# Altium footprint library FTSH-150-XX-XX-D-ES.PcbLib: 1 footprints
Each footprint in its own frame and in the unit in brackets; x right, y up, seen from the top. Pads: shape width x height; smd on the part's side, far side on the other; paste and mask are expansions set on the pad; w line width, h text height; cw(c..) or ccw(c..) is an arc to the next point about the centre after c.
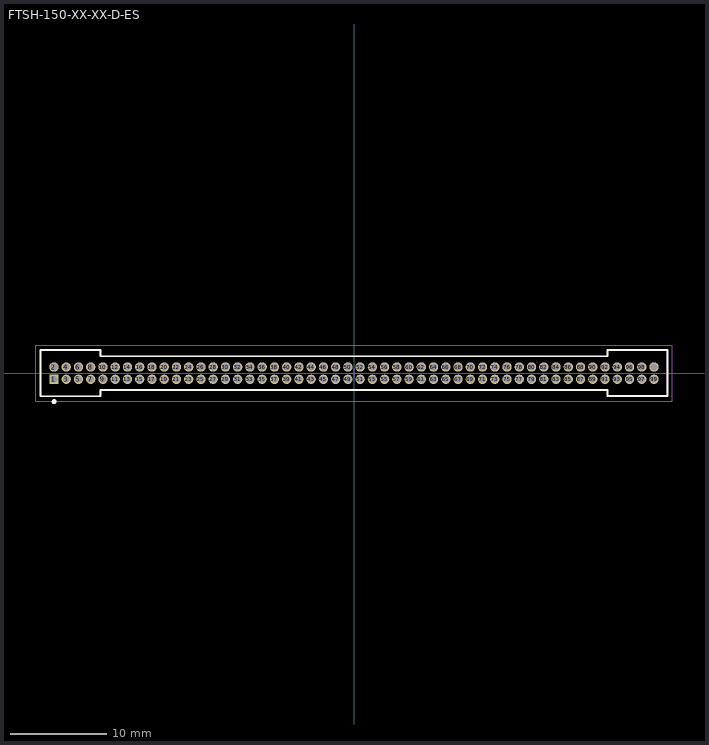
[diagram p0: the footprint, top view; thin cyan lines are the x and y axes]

## FTSH-150-XX-XX-D-ES [mil] "1.27mm pitch, 100 pin, terminal strip; w/end shrouds, PTH"
height 120.08
pads (100):
  rect 38x38 hole 28 unplated mask+0: 1(-1225,-25)
  round 38 hole 28 unplated mask+0: 2(-1225,25) 3(-1175,-25) 4(-1175,25) 5(-1125,-25) 6(-1125,25) 7(-1075,-25) 8(-1075,25) 9(-1025,-25) 10(-1025,25) 11(-975,-25) 12(-975,25) 13(-925,-25) 14(-925,25) 15(-875,-25) 16(-875,25) 17(-825,-25) 18(-825,25) 19(-775,-25) 20(-775,25) 21(-725,-25) 22(-725,25) 23(-675,-25) 24(-675,25) 25(-625,-25) 26(-625,25) 27(-575,-25) 28(-575,25) 29(-525,-25) 30(-525,25) 31(-475,-25) 32(-475,25) 33(-425,-25) 34(-425,25) 35(-375,-25) 36(-375,25) 37(-325,-25) 38(-325,25) 39(-275,-25) 40(-275,25) 41(-225,-25) 42(-225,25) 43(-175,-25) 44(-175,25) 45(-125,-25) 46(-125,25) 47(-75,-25) 48(-75,25) 49(-25,-25) 50(-25,25) 51(25,-25) 52(25,25) 53(75,-25) 54(75,25) 55(125,-25) 56(125,25) 57(175,-25) 58(175,25) 59(225,-25) 60(225,25) 61(275,-25) 62(275,25) 63(325,-25) 64(325,25) 65(375,-25) 66(375,25) 67(425,-25) 68(425,25) 69(475,-25) 70(475,25) 71(525,-25) 72(525,25) 73(575,-25) 74(575,25) 75(625,-25) 76(625,25) 77(675,-25) 78(675,25) 79(725,-25) 80(725,25) 81(775,-25) 82(775,25) 83(825,-25) 84(825,25) 85(875,-25) 86(875,25) 87(925,-25) 88(925,25) 89(975,-25) 90(975,25) 91(1025,-25) 92(1025,25) 93(1075,-25) 94(1075,25) 95(1125,-25) 96(1125,25) 97(1175,-25) 98(1175,25) 99(1225,-25) 100(1225,25)
Top Overlay:
  circle w9.84: c-1224.41,-116.14 r4.92
  lines w7.87: -1279.53,-94.49 -1279.53,94.49 -1035.43,94.49 -1035.43,68.9 1035.43,68.9 1035.43,94 1279.53,94 1279.53,-94 1035.43,-94 1035.43,-68.9 -1035.43,-68.9 -1035.43,-94.49 -1279.53,-94.49
Mechanical 12:
  lines w0.04: -1279.53,-94.49 -1279.53,94.49 -1035.43,94.49 -1035.43,68.9 1035.43,68.9 1035.43,94 1279.53,94 1279.53,-94 1035.43,-94 1035.43,-68.9 -1035.43,-68.9 -1035.43,-94.49 -1279.53,-94.49
Mechanical 13:
  lines w3.94: -1279.53,-94.49 -1279.53,94.49 -1035.43,94.49 -1035.43,68.9 1035.43,68.9 1035.43,94 1279.53,94 1279.53,-94 1035.43,-94 1035.43,-68.9 -1035.43,-68.9 -1035.43,-94.49 -1279.53,-94.49
  text ".Designator" at 10,10 h60
Mechanical 15:
  lines w1.97: -19.68,0 19.68,0 ; 0,-19.68 0,19.68 ; -1299.21,-114 -1299.21,114 1299.21,114 1299.21,-114 -1299.21,-114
